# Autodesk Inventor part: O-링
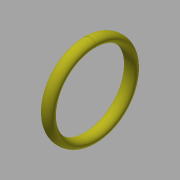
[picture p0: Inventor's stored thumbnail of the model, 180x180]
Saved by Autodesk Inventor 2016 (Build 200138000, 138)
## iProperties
Created: 2019-02
Part Number: O-링
Material: 고무
Document SubType Name: Modeling
Designer: mduedu
Density: 1 g/cm^3
Appearance: 밝은 황색
Author: mduedu
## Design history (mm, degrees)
sketch "스케치1"
  geometry: L1 (-2.35, 0)-(2.35, 0); L2 (2.35, 0)-(2.35, 17); L3 (2.35, 17)-(-2.35, 17); L4 (-2.35, 17)-(-2.35, 0); L5 (-2.35, 14)-(2.35, 14); 3 further points; 1 other entity
  constraints: 10 end point, 4 horizontal, 2 parallel, 2 perpendicular, 2 point on line, 2 vertical, 1 coincident, 1 midpoint, 2 other
  dimensions: "d0" = 34 diameter of L3 L1; "d2" = 4.7 distance of L2.end L3.end; "d3" = 28 diameter of L5 L1
revolve "회전1" sketch "스케치1" stored, may be unused: angle "d4" = 90 deg
node "솔리드1"
